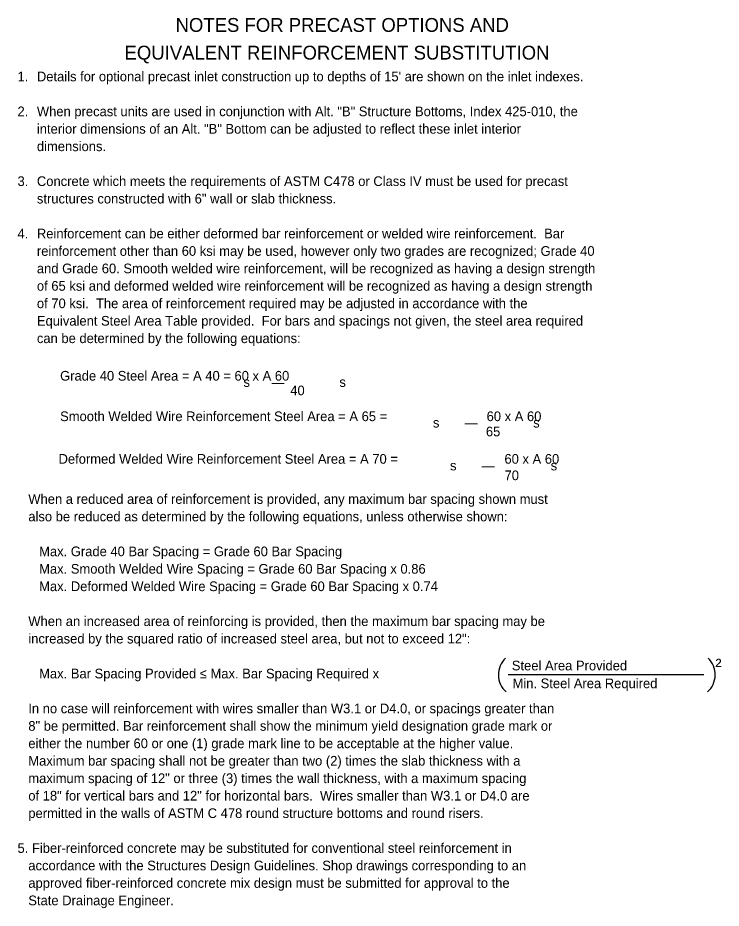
# Model space of a CAD drawing. Extents: x 10051 to 10780, y 10045 to 10510.
# Drawn here: x 10526.3 to 10780.3, y 10188.6 to 10510 of the extents above; entities that cross this region are included whole.
import ezdxf

# ---------------------------------------------------------------- set-up
doc = ezdxf.new("R2010")
doc.units = 0
doc.layers.add('Dimension', color=7, linetype='Continuous')

msp = doc.modelspace()

# ---------------------------------------------------------------- linework, layer by layer
at = {"layer": 'Dimension'}
msp.add_line((10703.4, 10272.94), (10774.01, 10272.94), dxfattribs=at)
for centre, start, end in [((10708.12, 10272.84), 133.5057, 228.3665), ((10769.81, 10272.84), 311.6335, 46.4943)]:
    msp.add_arc(centre, 8.3, start, end, dxfattribs=at)

# ---------------------------------------------------------------- texts
for s, height, p in [('NOTES FOR PRECAST OPTIONS AND ', 5, (10583.26, 10504.92)), ('EQUIVALENT REINFORCEMENT SUBSTITUTION', 5, (10564.83, 10494.92)), ('Grade 40 Steel Area = A 40 = 60 x A 60', 3.5, (10541.57, 10379.02)), ('s      ―', 3.5, (10607.76, 10376.74)), ('s', 3.5, (10642.4, 10376.74)), ('40', 3.5, (10624.67, 10373.73)), ('Smooth Welded Wire Reinforcement Steel Area = A 65 =', 3.5, (10541.57, 10364.4)), ('60 x A 60', 3.5, (10695.57, 10364.4)), ('s       ―', 3.5, (10676.19, 10362.09)), ('s', 3.5, (10712.38, 10362.09)), ('65', 3.5, (10695.31, 10358.9)), ('Deformed Welded Wire Reinforcement Steel Area = A 70 =', 3.5, (10541.01, 10349.02)), ('60 x A 60', 3.5, (10702.01, 10349.02)), ('s       ―', 3.5, (10682.36, 10346.62)), ('s', 3.5, (10718.7, 10346.62)), ('70', 3.5, (10702.04, 10343.08)), ('  Steel Area Provided   ', 3.5, (10702.07, 10274.42)), ('²', 5, (10778.17, 10273.61)), ('Min. Steel Area Required', 3.5, (10704.94, 10267.99))]:
    msp.add_text(s, height=height, dxfattribs=at).set_placement(p)
for s, p in [('1.', (10526.19, 10487.07)), ("Details for optional precast inlet construction up to depths of 15' are shown on the inlet indexes.", (10533.19, 10487.07)), ('2.', (10526.19, 10474.47)), ('When precast units are used in conjunction with Alt. "B" Structure Bottoms, Index 425-010, the ', (10533.19, 10474.47)), ('interior dimensions of an Alt. "B" Bottom can be adjusted to reflect these inlet interior ', (10533.19, 10468.17)), ('dimensions.', (10533.19, 10461.87)), ('3.', (10526.19, 10449.27)), ('Concrete which meets the requirements of ASTM C478 or Class IV must be used for precast ', (10533.19, 10449.27)), ('structures constructed with 6" wall or slab thickness.', (10533.19, 10442.97)), ('4.', (10526.19, 10430.37)), ('Reinforcement can be either deformed bar reinforcement or welded wire reinforcement.  Bar ', (10533.19, 10430.37)), ('reinforcement other than 60 ksi may be used, however only two grades are recognized; Grade 40 ', (10533.19, 10424.07)), ('and Grade 60. Smooth welded wire reinforcement, will be recognized as having a design strength ', (10533.19, 10417.77)), ('of 65 ksi and deformed welded wire reinforcement will be recognized as having a design strength ', (10533.19, 10411.47)), ('of 70 ksi.  The area of reinforcement required may be adjusted in accordance with the ', (10533.19, 10405.17)), ('Equivalent Steel Area Table provided.  For bars and spacings not given, the steel area required ', (10533.19, 10398.87)), ('can be determined by the following equations:', (10533.19, 10392.57)), ('   When a reduced area of reinforcement is provided, any maximum bar spacing shown must ', (10526.19, 10334.53)), ('   also be reduced as determined by the following equations, unless otherwise shown:', (10526.19, 10328.23)), ('      Max. Grade 40 Bar Spacing = Grade 60 Bar Spacing', (10526.19, 10315.63)), ('      Max. Smooth Welded Wire Spacing = Grade 60 Bar Spacing x 0.86', (10526.19, 10309.33)), ('      Max. Deformed Welded Wire Spacing = Grade 60 Bar Spacing x 0.74 ', (10526.19, 10303.03)), ('   When an increased area of reinforcing is provided, then the maximum bar spacing may be', (10526.19, 10290.43)), ('   increased by the squared ratio of increased steel area, but not to exceed 12":', (10526.19, 10284.13)), ('      Max. Bar Spacing Provided ≤ Max. Bar Spacing Required x ', (10526.19, 10271.53)), ('   In no case will reinforcement with wires smaller than W3.1 or D4.0, or spacings greater than ', (10526.19, 10258.93)), ('   8" be permitted. Bar reinforcement shall show the minimum yield designation grade mark or ', (10526.19, 10252.63)), ('   either the number 60 or one (1) grade mark line to be acceptable at the higher value.  ', (10526.19, 10246.33)), ('   Maximum bar spacing shall not be greater than two (2) times the slab thickness with a ', (10526.19, 10240.03)), ('   maximum spacing of 12" or three (3) times the wall thickness, with a maximum spacing ', (10526.19, 10233.73)), ('   of 18" for vertical bars and 12" for horizontal bars.  Wires smaller than W3.1 or D4.0 are', (10526.19, 10227.43)), ('   permitted in the walls of ASTM C 478 round structure bottoms and round risers.', (10526.19, 10221.13)), ('5. Fiber-reinforced concrete may be substituted for conventional steel reinforcement in ', (10526.19, 10208.53)), ('   accordance with the Structures Design Guidelines. Shop drawings corresponding to an ', (10526.19, 10202.23)), ('   approved fiber-reinforced concrete mix design must be submitted for approval to the ', (10526.19, 10195.93)), ('   State Drainage Engineer.', (10526.19, 10189.63))]:
    msp.add_text(s, height=3.5, rotation=0, dxfattribs=at).set_placement(p)

doc.saveas('drawing.dxf')
